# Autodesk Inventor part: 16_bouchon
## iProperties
Shininess: 20.0
Length Units: 11270
Angle Units: 11279
Time Units: 11290
Mass Units: 11283
Length Display Precision: 3
Angle Display Precision: 2
Created: 2000-10
Part Number: 16_bouchon
Material: Par défaut
Document SubType Name: Modélisation
Density: 0.0
Volumn: 0.0
Area: 0.0
PropertySet Name: Model Information
Control State: 0
Master: False
Checked Out: False
Author: Laurent GAUTHERON
